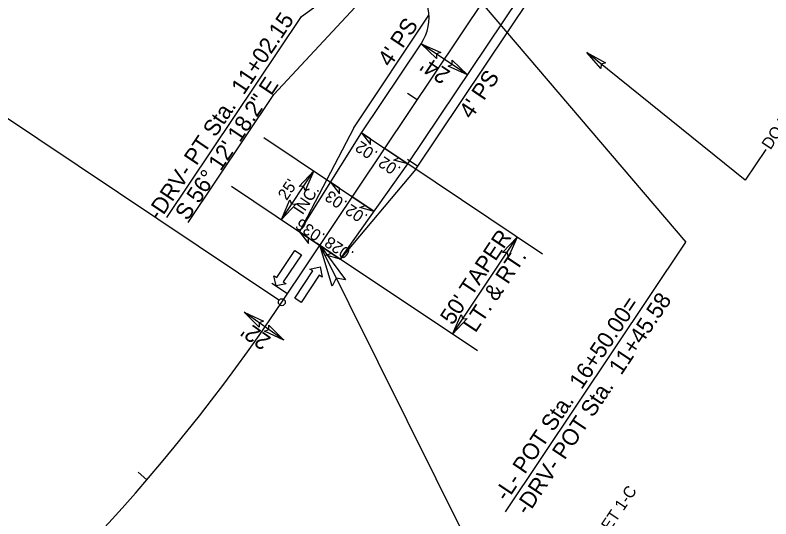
# Model space of a CAD drawing. Extents: x 1716813 to 1718091, y 800228 to 801730.
# Drawn here: x 1717290.1 to 1717614.3, y 800745.6 to 800961.6 of the extents above; entities that cross this region are included whole.
import ezdxf

# ---------------------------------------------------------------- set-up
doc = ezdxf.new("R2010")
doc.units = 0
for name, color, linetype in [('Prop Dimension', 7, 'Continuous'), ('Prop DSN Text', 7, 'Continuous'), ('Prop EOT', 7, 'Continuous'), ('Prop Horizontal Alignment', 7, 'Continuous'), ('Prop Horizontal Alignment Direction Label', 7, 'Continuous'), ('Prop Horizontal Alignment Station Label', 7, 'Continuous'), ('Prop Horizontal Alignment Tick Large', 7, 'Continuous'), ('Prop Horizontal Alignment Tick Small', 7, 'Continuous'), ('Prop Lane Arrow CELL', 7, 'Continuous'), ('Prop Paved Shoulder', 7, 'Continuous'), ('Prop Superelevation  Arrow CELL', 7, 'Continuous'), ('Prop Superelevation Label', 7, 'Continuous'), ('Prop Terminator CELL', 7, 'Continuous')]:
    doc.layers.add(name, color=color, linetype=linetype)

msp = doc.modelspace()

# ---------------------------------------------------------------- linework, layer by layer
at = {"layer": 'Prop Dimension'}
for p, q in [((1717484.18, 800935.98), (1717464.24, 800949.33)), ((1717396.73, 800909.08), (1717425.37, 800889.91)), ((1717516.28, 800859.15), (1717458.6, 800897.76)), ((1717404.3, 800873.99), (1717418.2, 800894.77)), ((1717382.9, 800888.25), (1717412.09, 800868.72)), ((1717477.66, 800824.83), (1717505.48, 800866.38)), ((1717420.81, 800862.88), (1717515.94, 800671.88)), ((1717488.46, 800817.6), (1717429.58, 800857.01)), ((1717405.4, 800822.19), (1717388.35, 800834.2))]:
    msp.add_line(p, q, dxfattribs=at)
at = {"layer": 'Prop DSN Text'}
for p, q in [((1717603.27, 800890.81), (1717535.29, 800945.53)), ((1717612.08, 800903.97), (1717603.27, 800890.81)), ((1717458.44, 800899.77), (1717462.81, 800896.85))]:
    msp.add_line(p, q, dxfattribs=at)
at = {"layer": 'Prop EOT'}
for p, q in [((1717458.6, 800897.76), (1717664.79, 801205.82)), ((1717438.65, 800911.1), (1717464.24, 800949.33)), ((1717412.09, 800868.72), (1717438.65, 800911.1)), ((1717429.58, 800857.01), (1717458.6, 800897.76))]:
    msp.add_line(p, q, dxfattribs=at)
msp.add_arc((1717447.62, 800960.46), 20, 326.2051, 56.2051, dxfattribs=at)
at = {"layer": 'Prop Horizontal Alignment'}
msp.add_line((1717404.5, 800838.5), (1717654.82, 801212.49), dxfattribs=at)
msp.add_arc((1716739.67, 801283.48), 800, 306.49907, 326.20506, dxfattribs=at)
at = {"layer": 'Prop Horizontal Alignment Direction Label'}
for p, q in [((1717401.02, 800927.49), (1717457.77, 800988.56)), ((1717364.37, 800872.73), (1717401.02, 800927.49))]:
    msp.add_line(p, q, dxfattribs=at)
at = {"layer": 'Prop Horizontal Alignment Station Label'}
for p, q in [((1717403.25, 800839.33), (1717175.96, 800991.46)), ((1717412.87, 800961.04), (1717453.03, 800990.03)), ((1717491.31, 800965.62), (1717577.75, 800864.17)), ((1717355.12, 800874.75), (1717412.87, 800961.04)), ((1717500.36, 800748.55), (1717577.75, 800864.17))]:
    msp.add_line(p, q, dxfattribs=at)
msp.add_circle((1717404.5, 800838.5), 1.5, dxfattribs=at)
at = {"layer": 'Prop Horizontal Alignment Tick Large'}
msp.add_line((1717406.91, 800842.1), (1717400.26, 800846.55), dxfattribs=at)
at = {"layer": 'Prop Horizontal Alignment Tick Small'}
for p, q in [((1717462.53, 800925.21), (1717458.38, 800927.99)), ((1717346.66, 800762.37), (1717342.87, 800765.62))]:
    msp.add_line(p, q, dxfattribs=at)
at = {"layer": 'Prop Lane Arrow CELL'}
for p, q in [((1717402.35, 800849.03), (1717410.14, 800860.67)), ((1717412.88, 800858.83), (1717405.1, 800847.2)), ((1717410.14, 800860.67), (1717412.88, 800858.83)), ((1717410.03, 800840.25), (1717417.82, 800851.89)), ((1717416.57, 800852.72), (1717420.9, 800853.62)), ((1717417.82, 800851.89), (1717416.57, 800852.72)), ((1717420.9, 800853.62), (1717421.8, 800849.22)), ((1717402.01, 800845.47), (1717401.11, 800849.86)), ((1717401.11, 800849.86), (1717402.35, 800849.03)), ((1717420.56, 800850.05), (1717412.77, 800838.42)), ((1717421.8, 800849.22), (1717420.56, 800850.05)), ((1717406.34, 800846.36), (1717402.01, 800845.47)), ((1717405.1, 800847.2), (1717406.34, 800846.36)), ((1717412.77, 800838.42), (1717410.03, 800840.25))]:
    msp.add_line(p, q, dxfattribs=at)
at = {"layer": 'Prop Paved Shoulder'}
for p, q in [((1717461.92, 800895.53), (1717547.01, 801022.66)), ((1717435.33, 800913.33), (1717467.59, 800961.53)), ((1717435.33, 800913.33), (1717412.09, 800868.72)), ((1717461.92, 800895.53), (1717429.58, 800857.01))]:
    msp.add_line(p, q, dxfattribs=at)
at = {"layer": 'Prop Superelevation  Arrow CELL'}
for p, q in [((1717438.65, 800911.1), (1717448.62, 800904.43)), ((1717458.6, 800897.76), (1717448.62, 800904.43)), ((1717425.37, 800889.91), (1717435.34, 800883.24)), ((1717444.09, 800877.38), (1717434.12, 800884.06)), ((1717412.09, 800868.72), (1717422.06, 800862.04)), ((1717429.58, 800857.01), (1717419.61, 800863.69))]:
    msp.add_line(p, q, dxfattribs=at)
for points in [[(1717438.65, 800911.1), (1717442.53, 800906.1), (1717442.5, 800908.53)], [(1717458.6, 800897.76), (1717452.5, 800899.43), (1717454.75, 800900.33)], [(1717425.37, 800889.91), (1717429.24, 800884.91), (1717429.21, 800887.34)], [(1717444.09, 800877.38), (1717437.99, 800879.06), (1717440.25, 800879.96)], [(1717412.09, 800868.72), (1717415.96, 800863.72), (1717415.93, 800866.15)], [(1717429.58, 800857.01), (1717423.48, 800858.69), (1717425.74, 800859.58)]]:
    msp.add_lwpolyline(points, close=True, dxfattribs=at)
at = {"layer": 'Prop Superelevation Label'}
for p, q in [((1717438.65, 800911.1), (1717458.6, 800897.76)), ((1717425.37, 800889.91), (1717444.09, 800877.38)), ((1717412.09, 800868.72), (1717429.58, 800857.01))]:
    msp.add_line(p, q, dxfattribs=at)
at = {"layer": 'Prop Terminator CELL'}
for points in [[(1717470.86, 800943.04), (1717464.24, 800949.33), (1717472.65, 800945.63), (1717470.8, 800944.94)], [(1717541.33, 800938.68), (1717535.29, 800945.53), (1717543.34, 800941.11), (1717541.44, 800940.58)], [(1717477.57, 800942.28), (1717484.18, 800935.98), (1717475.77, 800939.69), (1717477.62, 800940.38)], [(1717411.91, 800888.15), (1717418.2, 800894.77), (1717414.5, 800886.36), (1717413.81, 800888.2)], [(1717410.59, 800880.61), (1717404.3, 800873.99), (1717408, 800882.4), (1717408.69, 800880.56)], [(1717499.18, 800859.76), (1717505.48, 800866.38), (1717501.77, 800857.97), (1717501.08, 800859.81)], [(1717426.06, 800845.38), (1717420.81, 800862.88), (1717431.75, 800848.1), (1717427.86, 800848.74)], [(1717394.81, 800827.75), (1717388.35, 800834.2), (1717396.67, 800830.3), (1717394.81, 800829.65)], [(1717483.96, 800831.44), (1717477.66, 800824.83), (1717481.37, 800833.24), (1717482.06, 800831.39)], [(1717398.94, 800828.64), (1717405.4, 800822.19), (1717397.08, 800826.09), (1717398.95, 800826.74)]]:
    msp.add_lwpolyline(points, close=True, dxfattribs=at)

# ---------------------------------------------------------------- texts
at = {"layer": 'Prop Dimension'}
for s, height, rotation, p in [("4' PS", 7, 56.2051, (1717450.97, 800938.97)), ("24'", 7, 146.2051, (1717477.21, 800937.33)), ("4' PS", 7, 56.2051, (1717485.82, 800916.63)), ("25'", 5, 56.2051, (1717406.57, 800881.82)), ('INC.', 5, 56.2051, (1717413.37, 800875.65)), ("50' TAPER", 7, 56.2051, (1717477.73, 800828.33)), ('LT. & RT.', 7, 56.2051, (1717487.53, 800825.05)), ("22'", 7, 144.8262, (1717400.28, 800823.15))]:
    msp.add_text(s, height=height, rotation=rotation, dxfattribs=at).set_placement(p)
at = {"layer": 'Prop DSN Text'}
for s, p in [('DO NOT DISTURB', (1717614.06, 800903.55)), ('SEE SHEET 1-C', (1717529.09, 800716.02))]:
    msp.add_text(s, height=5, rotation=56.2051, dxfattribs=at).set_placement(p)
at = {"layer": 'Prop Horizontal Alignment Direction Label'}
msp.add_text('S 56%%d 12\' 18.2" E', height=7, rotation=56.2051, dxfattribs=at).set_placement((1717364.03, 800873.1))
at = {"layer": 'Prop Horizontal Alignment Station Label'}
for s, rotation, p in [('-DRV- PT Sta.  11+02.15', 56.2051, (1717351.97, 800872.99)), ('-DRV- POT Sta.  11+45.58', 56.205, (1717509.85, 800746.8)), ('-L- POT Sta.  16+50.00=', 56.205, (1717500.96, 800752.75))]:
    msp.add_text(s, height=7, rotation=rotation, dxfattribs=at).set_placement(p)
at = {"layer": 'Prop Superelevation Label'}
for s, p in [('.02', (1717445.97, 800902.73)), ('.02', (1717455.89, 800896.1)), ('.03', (1717432.94, 800881.49)), ('.02', (1717441.73, 800875.67)), ('.036', (1717423.43, 800867.45)), ('.028', (1717435.85, 800859.78))]:
    msp.add_text(s, height=5, rotation=146.2051, dxfattribs=at).set_placement(p)

doc.saveas('drawing.dxf')
